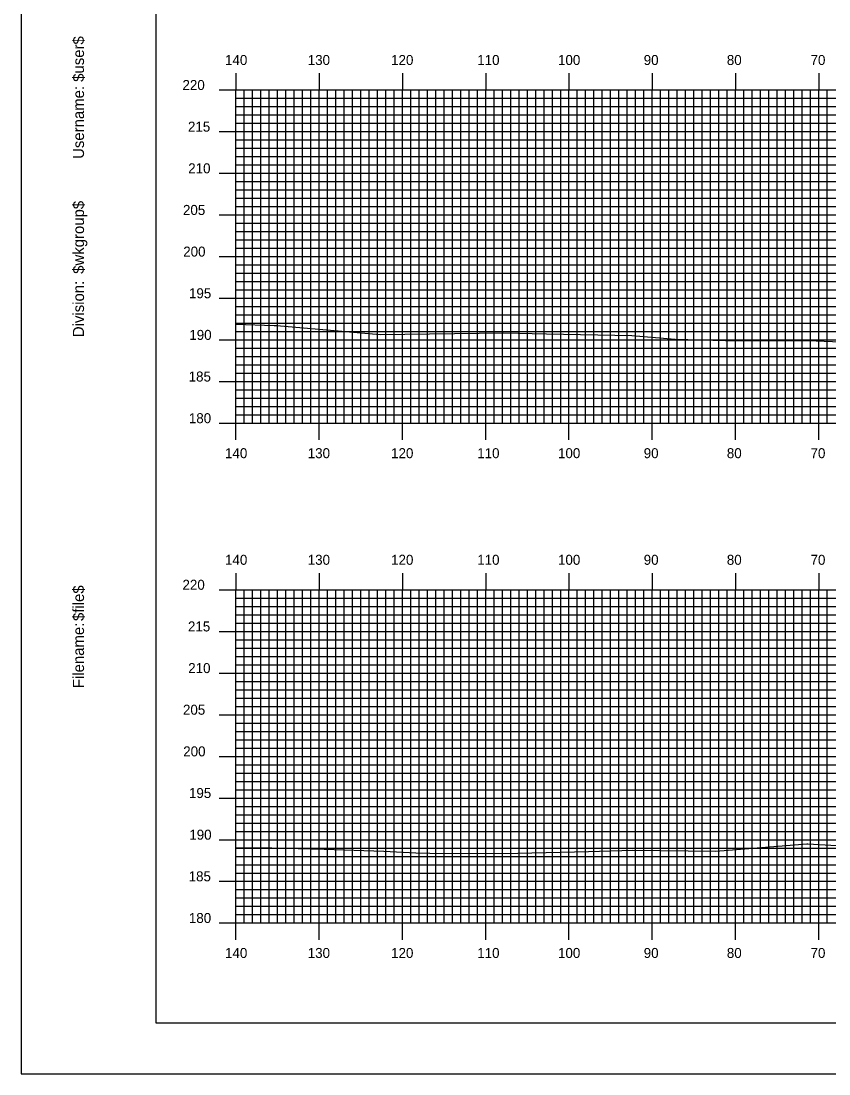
# Model space of a CAD drawing. Extents: x 1810587 to 1810930, y 442591 to 442811.
# Drawn here: x 1810586.6 to 1810683.6, y 442590.5 to 442716.9 of the extents above; entities that cross this region are included whole.
import ezdxf

# ---------------------------------------------------------------- set-up
doc = ezdxf.new("R2010")
doc.units = 0
for name, color, linetype in [('BORDER', 7, 'Continuous'), ('H_V ANNOTATION', 7, 'Continuous'), ('MAJOR', 7, 'Continuous'), ('MINOR', 7, 'Continuous'), ('PLOT BOUNDARY', 7, 'Continuous'), ('S_Roadway_Centerline', 7, 'Continuous')]:
    doc.layers.add(name, color=color, linetype=linetype)

msp = doc.modelspace()

# ---------------------------------------------------------------- linework, layer by layer
at = {"layer": 'BORDER'}
msp.add_lwpolyline([(1810602.78, 442596.67), (1810922.78, 442596.67), (1810922.78, 442806.67), (1810602.78, 442806.67)], close=True, dxfattribs=at)
at = {"layer": 'MAJOR'}
for p, q in [((1810612.38, 442710.67), (1810612.38, 442708.67)), ((1810622.38, 442710.67), (1810622.38, 442708.67)), ((1810632.38, 442710.67), (1810632.38, 442708.67)), ((1810642.38, 442710.67), (1810642.38, 442708.67)), ((1810652.38, 442710.67), (1810652.38, 442708.67)), ((1810662.38, 442710.67), (1810662.38, 442708.67)), ((1810672.38, 442710.67), (1810672.38, 442708.67)), ((1810682.38, 442710.67), (1810682.38, 442708.67)), ((1810610.37, 442708.67), (1810612.38, 442708.67)), ((1810612.38, 442708.67), (1810892.38, 442708.67)), ((1810612.38, 442668.67), (1810612.38, 442708.67)), ((1810612.38, 442668.67), (1810612.38, 442708.67)), ((1810612.38, 442708.67), (1810892.38, 442708.67)), ((1810622.38, 442668.67), (1810622.38, 442708.67)), ((1810632.38, 442668.67), (1810632.38, 442708.67)), ((1810642.38, 442668.67), (1810642.38, 442708.67)), ((1810652.38, 442668.67), (1810652.38, 442708.67)), ((1810662.38, 442668.67), (1810662.38, 442708.67)), ((1810672.38, 442668.67), (1810672.38, 442708.67)), ((1810682.38, 442668.67), (1810682.38, 442708.67)), ((1810610.37, 442703.67), (1810612.38, 442703.67)), ((1810612.38, 442703.67), (1810892.38, 442703.67)), ((1810610.37, 442698.67), (1810612.38, 442698.67)), ((1810612.38, 442698.67), (1810892.38, 442698.67)), ((1810610.37, 442693.67), (1810612.38, 442693.67)), ((1810612.38, 442693.67), (1810892.38, 442693.67)), ((1810610.37, 442688.67), (1810612.38, 442688.67)), ((1810612.38, 442688.67), (1810892.38, 442688.67)), ((1810610.37, 442683.67), (1810612.38, 442683.67)), ((1810612.38, 442683.67), (1810892.38, 442683.67)), ((1810610.37, 442678.67), (1810612.38, 442678.67)), ((1810612.38, 442678.67), (1810892.38, 442678.67)), ((1810610.37, 442673.67), (1810612.38, 442673.67)), ((1810612.38, 442673.67), (1810892.38, 442673.67)), ((1810610.37, 442668.67), (1810612.38, 442668.67)), ((1810612.38, 442668.67), (1810892.38, 442668.67)), ((1810612.38, 442668.67), (1810892.38, 442668.67)), ((1810612.38, 442666.66), (1810612.38, 442668.67)), ((1810622.38, 442666.66), (1810622.38, 442668.67)), ((1810632.38, 442666.66), (1810632.38, 442668.67)), ((1810642.38, 442666.66), (1810642.38, 442668.67)), ((1810652.38, 442666.66), (1810652.38, 442668.67)), ((1810662.38, 442666.66), (1810662.38, 442668.67)), ((1810672.38, 442666.66), (1810672.38, 442668.67)), ((1810682.38, 442666.66), (1810682.38, 442668.67)), ((1810612.38, 442650.67), (1810612.38, 442648.67)), ((1810622.38, 442650.67), (1810622.38, 442648.67)), ((1810632.38, 442650.67), (1810632.38, 442648.67)), ((1810642.38, 442650.67), (1810642.38, 442648.67)), ((1810652.38, 442650.67), (1810652.38, 442648.67)), ((1810662.38, 442650.67), (1810662.38, 442648.67)), ((1810672.38, 442650.67), (1810672.38, 442648.67)), ((1810682.38, 442650.67), (1810682.38, 442648.67)), ((1810610.37, 442648.67), (1810612.38, 442648.67)), ((1810612.38, 442648.67), (1810892.38, 442648.67)), ((1810612.38, 442608.67), (1810612.38, 442648.67)), ((1810612.38, 442608.67), (1810612.38, 442648.67)), ((1810612.38, 442648.67), (1810892.38, 442648.67)), ((1810622.38, 442608.67), (1810622.38, 442648.67)), ((1810632.38, 442608.67), (1810632.38, 442648.67)), ((1810642.38, 442608.67), (1810642.38, 442648.67)), ((1810652.38, 442608.67), (1810652.38, 442648.67)), ((1810662.38, 442608.67), (1810662.38, 442648.67)), ((1810672.38, 442608.67), (1810672.38, 442648.67)), ((1810682.38, 442608.67), (1810682.38, 442648.67)), ((1810610.37, 442643.67), (1810612.38, 442643.67)), ((1810612.38, 442643.67), (1810892.38, 442643.67)), ((1810610.37, 442638.67), (1810612.38, 442638.67)), ((1810612.38, 442638.67), (1810892.38, 442638.67)), ((1810610.37, 442633.67), (1810612.38, 442633.67)), ((1810612.38, 442633.67), (1810892.38, 442633.67)), ((1810610.37, 442628.67), (1810612.38, 442628.67)), ((1810612.38, 442628.67), (1810892.38, 442628.67)), ((1810610.37, 442623.67), (1810612.38, 442623.67)), ((1810612.38, 442623.67), (1810892.38, 442623.67)), ((1810610.37, 442618.67), (1810612.38, 442618.67)), ((1810612.38, 442618.67), (1810892.38, 442618.67)), ((1810610.37, 442613.67), (1810612.38, 442613.67)), ((1810612.38, 442613.67), (1810892.38, 442613.67)), ((1810610.37, 442608.67), (1810612.38, 442608.67)), ((1810612.38, 442608.67), (1810892.38, 442608.67)), ((1810612.38, 442608.67), (1810892.38, 442608.67)), ((1810612.38, 442606.66), (1810612.38, 442608.67)), ((1810622.38, 442606.66), (1810622.38, 442608.67)), ((1810632.38, 442606.66), (1810632.38, 442608.67)), ((1810642.38, 442606.66), (1810642.38, 442608.67)), ((1810652.38, 442606.66), (1810652.38, 442608.67)), ((1810662.38, 442606.66), (1810662.38, 442608.67)), ((1810672.38, 442606.66), (1810672.38, 442608.67)), ((1810682.38, 442606.66), (1810682.38, 442608.67))]:
    msp.add_line(p, q, dxfattribs=at)
at = {"layer": 'MINOR'}
for p, q in [((1810613.38, 442668.67), (1810613.38, 442708.67)), ((1810614.38, 442668.67), (1810614.38, 442708.67)), ((1810615.38, 442668.67), (1810615.38, 442708.67)), ((1810616.38, 442668.67), (1810616.38, 442708.67)), ((1810617.38, 442668.67), (1810617.38, 442708.67)), ((1810618.38, 442668.67), (1810618.38, 442708.67)), ((1810619.38, 442668.67), (1810619.38, 442708.67)), ((1810620.38, 442668.67), (1810620.38, 442708.67)), ((1810621.38, 442668.67), (1810621.38, 442708.67)), ((1810623.38, 442668.67), (1810623.38, 442708.67)), ((1810624.38, 442668.67), (1810624.38, 442708.67)), ((1810625.38, 442668.67), (1810625.38, 442708.67)), ((1810626.38, 442668.67), (1810626.38, 442708.67)), ((1810627.38, 442668.67), (1810627.38, 442708.67)), ((1810628.38, 442668.67), (1810628.38, 442708.67)), ((1810629.38, 442668.67), (1810629.38, 442708.67)), ((1810630.38, 442668.67), (1810630.38, 442708.67)), ((1810631.38, 442668.67), (1810631.38, 442708.67)), ((1810633.38, 442668.67), (1810633.38, 442708.67)), ((1810634.38, 442668.67), (1810634.38, 442708.67)), ((1810635.38, 442668.67), (1810635.38, 442708.67)), ((1810636.38, 442668.67), (1810636.38, 442708.67)), ((1810637.38, 442668.67), (1810637.38, 442708.67)), ((1810638.38, 442668.67), (1810638.38, 442708.67)), ((1810639.38, 442668.67), (1810639.38, 442708.67)), ((1810640.38, 442668.67), (1810640.38, 442708.67)), ((1810641.38, 442668.67), (1810641.38, 442708.67)), ((1810643.38, 442668.67), (1810643.38, 442708.67)), ((1810644.38, 442668.67), (1810644.38, 442708.67)), ((1810645.38, 442668.67), (1810645.38, 442708.67)), ((1810646.38, 442668.67), (1810646.38, 442708.67)), ((1810647.38, 442668.67), (1810647.38, 442708.67)), ((1810648.38, 442668.67), (1810648.38, 442708.67)), ((1810649.38, 442668.67), (1810649.38, 442708.67)), ((1810650.38, 442668.67), (1810650.38, 442708.67)), ((1810651.38, 442668.67), (1810651.38, 442708.67)), ((1810653.38, 442668.67), (1810653.38, 442708.67)), ((1810654.38, 442668.67), (1810654.38, 442708.67)), ((1810655.38, 442668.67), (1810655.38, 442708.67)), ((1810656.38, 442668.67), (1810656.38, 442708.67)), ((1810657.38, 442668.67), (1810657.38, 442708.67)), ((1810658.38, 442668.67), (1810658.38, 442708.67)), ((1810659.38, 442668.67), (1810659.38, 442708.67)), ((1810660.38, 442668.67), (1810660.38, 442708.67)), ((1810661.38, 442668.67), (1810661.38, 442708.67)), ((1810663.38, 442668.67), (1810663.38, 442708.67)), ((1810664.38, 442668.67), (1810664.38, 442708.67)), ((1810665.38, 442668.67), (1810665.38, 442708.67)), ((1810666.38, 442668.67), (1810666.38, 442708.67)), ((1810667.38, 442668.67), (1810667.38, 442708.67)), ((1810668.38, 442668.67), (1810668.38, 442708.67)), ((1810669.38, 442668.67), (1810669.38, 442708.67)), ((1810670.38, 442668.67), (1810670.38, 442708.67)), ((1810671.38, 442668.67), (1810671.38, 442708.67)), ((1810673.38, 442668.67), (1810673.38, 442708.67)), ((1810674.38, 442668.67), (1810674.38, 442708.67)), ((1810675.38, 442668.67), (1810675.38, 442708.67)), ((1810676.38, 442668.67), (1810676.38, 442708.67)), ((1810677.38, 442668.67), (1810677.38, 442708.67)), ((1810678.38, 442668.67), (1810678.38, 442708.67)), ((1810679.38, 442668.67), (1810679.38, 442708.67)), ((1810680.38, 442668.67), (1810680.38, 442708.67)), ((1810681.38, 442668.67), (1810681.38, 442708.67)), ((1810683.38, 442668.67), (1810683.38, 442708.67)), ((1810612.38, 442707.67), (1810892.38, 442707.67)), ((1810612.38, 442707.67), (1810614.38, 442707.67)), ((1810612.38, 442706.67), (1810892.38, 442706.67)), ((1810612.38, 442706.67), (1810614.38, 442706.67)), ((1810612.38, 442705.67), (1810892.38, 442705.67)), ((1810612.38, 442705.67), (1810614.38, 442705.67)), ((1810612.38, 442704.67), (1810892.38, 442704.67)), ((1810612.38, 442704.67), (1810614.38, 442704.67)), ((1810612.38, 442702.67), (1810892.38, 442702.67)), ((1810612.38, 442702.67), (1810614.38, 442702.67)), ((1810612.38, 442701.67), (1810892.38, 442701.67)), ((1810612.38, 442701.67), (1810614.38, 442701.67)), ((1810612.38, 442700.67), (1810892.38, 442700.67)), ((1810612.38, 442700.67), (1810614.38, 442700.67)), ((1810612.38, 442699.67), (1810892.38, 442699.67)), ((1810612.38, 442699.67), (1810614.38, 442699.67)), ((1810612.38, 442697.67), (1810892.38, 442697.67)), ((1810612.38, 442697.67), (1810614.38, 442697.67)), ((1810612.38, 442696.67), (1810892.38, 442696.67)), ((1810612.38, 442696.67), (1810614.38, 442696.67)), ((1810612.38, 442695.67), (1810892.38, 442695.67)), ((1810612.38, 442695.67), (1810614.38, 442695.67)), ((1810612.38, 442694.67), (1810892.38, 442694.67)), ((1810612.38, 442694.67), (1810614.38, 442694.67)), ((1810612.38, 442692.67), (1810892.38, 442692.67)), ((1810612.38, 442692.67), (1810614.38, 442692.67)), ((1810612.38, 442691.67), (1810892.38, 442691.67)), ((1810612.38, 442691.67), (1810614.38, 442691.67)), ((1810612.38, 442690.67), (1810892.38, 442690.67)), ((1810612.38, 442690.67), (1810614.38, 442690.67)), ((1810612.38, 442689.67), (1810892.38, 442689.67)), ((1810612.38, 442689.67), (1810614.38, 442689.67)), ((1810612.38, 442687.67), (1810892.38, 442687.67)), ((1810612.38, 442687.67), (1810614.38, 442687.67)), ((1810612.38, 442686.67), (1810892.38, 442686.67)), ((1810612.38, 442686.67), (1810614.38, 442686.67)), ((1810612.38, 442685.67), (1810892.38, 442685.67)), ((1810612.38, 442685.67), (1810614.38, 442685.67)), ((1810612.38, 442684.67), (1810892.38, 442684.67)), ((1810612.38, 442684.67), (1810614.38, 442684.67)), ((1810612.38, 442682.67), (1810892.38, 442682.67)), ((1810612.38, 442682.67), (1810614.38, 442682.67)), ((1810612.38, 442681.67), (1810892.38, 442681.67)), ((1810612.38, 442681.67), (1810614.38, 442681.67)), ((1810612.38, 442680.67), (1810892.38, 442680.67)), ((1810612.38, 442680.67), (1810614.38, 442680.67)), ((1810612.38, 442679.67), (1810892.38, 442679.67)), ((1810612.38, 442679.67), (1810614.38, 442679.67)), ((1810612.38, 442677.67), (1810892.38, 442677.67)), ((1810612.38, 442677.67), (1810614.38, 442677.67)), ((1810612.38, 442676.67), (1810892.38, 442676.67)), ((1810612.38, 442676.67), (1810614.38, 442676.67)), ((1810612.38, 442675.67), (1810892.38, 442675.67)), ((1810612.38, 442675.67), (1810614.38, 442675.67)), ((1810612.38, 442674.67), (1810892.38, 442674.67)), ((1810612.38, 442674.67), (1810614.38, 442674.67)), ((1810612.38, 442672.67), (1810892.38, 442672.67)), ((1810612.38, 442672.67), (1810614.38, 442672.67)), ((1810612.38, 442671.67), (1810892.38, 442671.67)), ((1810612.38, 442671.67), (1810614.38, 442671.67)), ((1810612.38, 442670.67), (1810892.38, 442670.67)), ((1810612.38, 442670.67), (1810614.38, 442670.67)), ((1810612.38, 442669.67), (1810892.38, 442669.67)), ((1810612.38, 442669.67), (1810614.38, 442669.67)), ((1810613.38, 442608.67), (1810613.38, 442648.67)), ((1810614.38, 442608.67), (1810614.38, 442648.67)), ((1810615.38, 442608.67), (1810615.38, 442648.67)), ((1810616.38, 442608.67), (1810616.38, 442648.67)), ((1810617.38, 442608.67), (1810617.38, 442648.67)), ((1810618.38, 442608.67), (1810618.38, 442648.67)), ((1810619.38, 442608.67), (1810619.38, 442648.67)), ((1810620.38, 442608.67), (1810620.38, 442648.67)), ((1810621.38, 442608.67), (1810621.38, 442648.67)), ((1810623.38, 442608.67), (1810623.38, 442648.67)), ((1810624.38, 442608.67), (1810624.38, 442648.67)), ((1810625.38, 442608.67), (1810625.38, 442648.67)), ((1810626.38, 442608.67), (1810626.38, 442648.67)), ((1810627.38, 442608.67), (1810627.38, 442648.67)), ((1810628.38, 442608.67), (1810628.38, 442648.67)), ((1810629.38, 442608.67), (1810629.38, 442648.67)), ((1810630.38, 442608.67), (1810630.38, 442648.67)), ((1810631.38, 442608.67), (1810631.38, 442648.67)), ((1810633.38, 442608.67), (1810633.38, 442648.67)), ((1810634.38, 442608.67), (1810634.38, 442648.67)), ((1810635.38, 442608.67), (1810635.38, 442648.67)), ((1810636.38, 442608.67), (1810636.38, 442648.67)), ((1810637.38, 442608.67), (1810637.38, 442648.67)), ((1810638.38, 442608.67), (1810638.38, 442648.67)), ((1810639.38, 442608.67), (1810639.38, 442648.67)), ((1810640.38, 442608.67), (1810640.38, 442648.67)), ((1810641.38, 442608.67), (1810641.38, 442648.67)), ((1810643.38, 442608.67), (1810643.38, 442648.67)), ((1810644.38, 442608.67), (1810644.38, 442648.67)), ((1810645.38, 442608.67), (1810645.38, 442648.67)), ((1810646.38, 442608.67), (1810646.38, 442648.67)), ((1810647.38, 442608.67), (1810647.38, 442648.67)), ((1810648.38, 442608.67), (1810648.38, 442648.67)), ((1810649.38, 442608.67), (1810649.38, 442648.67)), ((1810650.38, 442608.67), (1810650.38, 442648.67)), ((1810651.38, 442608.67), (1810651.38, 442648.67)), ((1810653.38, 442608.67), (1810653.38, 442648.67)), ((1810654.38, 442608.67), (1810654.38, 442648.67)), ((1810655.38, 442608.67), (1810655.38, 442648.67)), ((1810656.38, 442608.67), (1810656.38, 442648.67)), ((1810657.38, 442608.67), (1810657.38, 442648.67)), ((1810658.38, 442608.67), (1810658.38, 442648.67)), ((1810659.38, 442608.67), (1810659.38, 442648.67)), ((1810660.38, 442608.67), (1810660.38, 442648.67)), ((1810661.38, 442608.67), (1810661.38, 442648.67)), ((1810663.38, 442608.67), (1810663.38, 442648.67)), ((1810664.38, 442608.67), (1810664.38, 442648.67)), ((1810665.38, 442608.67), (1810665.38, 442648.67)), ((1810666.38, 442608.67), (1810666.38, 442648.67)), ((1810667.38, 442608.67), (1810667.38, 442648.67)), ((1810668.38, 442608.67), (1810668.38, 442648.67)), ((1810669.38, 442608.67), (1810669.38, 442648.67)), ((1810670.38, 442608.67), (1810670.38, 442648.67)), ((1810671.38, 442608.67), (1810671.38, 442648.67)), ((1810673.38, 442608.67), (1810673.38, 442648.67)), ((1810674.38, 442608.67), (1810674.38, 442648.67)), ((1810675.38, 442608.67), (1810675.38, 442648.67)), ((1810676.38, 442608.67), (1810676.38, 442648.67)), ((1810677.38, 442608.67), (1810677.38, 442648.67)), ((1810678.38, 442608.67), (1810678.38, 442648.67)), ((1810679.38, 442608.67), (1810679.38, 442648.67)), ((1810680.38, 442608.67), (1810680.38, 442648.67)), ((1810681.38, 442608.67), (1810681.38, 442648.67)), ((1810683.38, 442608.67), (1810683.38, 442648.67)), ((1810612.38, 442647.67), (1810892.38, 442647.67)), ((1810612.38, 442647.67), (1810614.38, 442647.67)), ((1810612.38, 442646.67), (1810892.38, 442646.67)), ((1810612.38, 442646.67), (1810614.38, 442646.67)), ((1810612.38, 442645.67), (1810892.38, 442645.67)), ((1810612.38, 442645.67), (1810614.38, 442645.67)), ((1810612.38, 442644.67), (1810892.38, 442644.67)), ((1810612.38, 442644.67), (1810614.38, 442644.67)), ((1810612.38, 442642.67), (1810892.38, 442642.67)), ((1810612.38, 442642.67), (1810614.38, 442642.67)), ((1810612.38, 442641.67), (1810892.38, 442641.67)), ((1810612.38, 442641.67), (1810614.38, 442641.67)), ((1810612.38, 442640.67), (1810892.38, 442640.67)), ((1810612.38, 442640.67), (1810614.38, 442640.67)), ((1810612.38, 442639.67), (1810892.38, 442639.67)), ((1810612.38, 442639.67), (1810614.38, 442639.67)), ((1810612.38, 442637.67), (1810892.38, 442637.67)), ((1810612.38, 442637.67), (1810614.38, 442637.67)), ((1810612.38, 442636.67), (1810892.38, 442636.67)), ((1810612.38, 442636.67), (1810614.38, 442636.67)), ((1810612.38, 442635.67), (1810892.38, 442635.67)), ((1810612.38, 442635.67), (1810614.38, 442635.67)), ((1810612.38, 442634.67), (1810892.38, 442634.67)), ((1810612.38, 442634.67), (1810614.38, 442634.67)), ((1810612.38, 442632.67), (1810892.38, 442632.67)), ((1810612.38, 442632.67), (1810614.38, 442632.67)), ((1810612.38, 442631.67), (1810892.38, 442631.67)), ((1810612.38, 442631.67), (1810614.38, 442631.67)), ((1810612.38, 442630.67), (1810892.38, 442630.67)), ((1810612.38, 442630.67), (1810614.38, 442630.67)), ((1810612.38, 442629.67), (1810892.38, 442629.67)), ((1810612.38, 442629.67), (1810614.38, 442629.67)), ((1810612.38, 442627.67), (1810892.38, 442627.67)), ((1810612.38, 442627.67), (1810614.38, 442627.67)), ((1810612.38, 442626.67), (1810892.38, 442626.67)), ((1810612.38, 442626.67), (1810614.38, 442626.67)), ((1810612.38, 442625.67), (1810892.38, 442625.67)), ((1810612.38, 442625.67), (1810614.38, 442625.67)), ((1810612.38, 442624.67), (1810892.38, 442624.67)), ((1810612.38, 442624.67), (1810614.38, 442624.67)), ((1810612.38, 442622.67), (1810892.38, 442622.67)), ((1810612.38, 442622.67), (1810614.38, 442622.67)), ((1810612.38, 442621.67), (1810892.38, 442621.67)), ((1810612.38, 442621.67), (1810614.38, 442621.67)), ((1810612.38, 442620.67), (1810892.38, 442620.67)), ((1810612.38, 442620.67), (1810614.38, 442620.67)), ((1810612.38, 442619.67), (1810892.38, 442619.67)), ((1810612.38, 442619.67), (1810614.38, 442619.67)), ((1810612.38, 442617.67), (1810892.38, 442617.67)), ((1810612.38, 442617.67), (1810614.38, 442617.67)), ((1810612.38, 442616.67), (1810892.38, 442616.67)), ((1810612.38, 442616.67), (1810614.38, 442616.67)), ((1810612.38, 442615.67), (1810892.38, 442615.67)), ((1810612.38, 442615.67), (1810614.38, 442615.67)), ((1810612.38, 442614.67), (1810892.38, 442614.67)), ((1810612.38, 442614.67), (1810614.38, 442614.67)), ((1810612.38, 442612.67), (1810892.38, 442612.67)), ((1810612.38, 442612.67), (1810614.38, 442612.67)), ((1810612.38, 442611.67), (1810892.38, 442611.67)), ((1810612.38, 442611.67), (1810614.38, 442611.67)), ((1810612.38, 442610.67), (1810892.38, 442610.67)), ((1810612.38, 442610.67), (1810614.38, 442610.67)), ((1810612.38, 442609.67), (1810892.38, 442609.67)), ((1810612.38, 442609.67), (1810614.38, 442609.67))]:
    msp.add_line(p, q, dxfattribs=at)
at = {"layer": 'PLOT BOUNDARY'}
msp.add_lwpolyline([(1810586.59, 442590.55), (1810926.59, 442590.55), (1810926.59, 442810.55), (1810586.59, 442810.55)], close=True, dxfattribs=at)
at = {"layer": 'S_Roadway_Centerline'}
for points in [[(1810612.38, 442680.56), (1810616.99, 442680.41), (1810617.32, 442680.39), (1810629.69, 442679.32), (1810644.57, 442679.5), (1810649.67, 442679.4), (1810659.94, 442679.19), (1810665.13, 442678.75), (1810671.18, 442678.59), (1810681.07, 442678.59), (1810695.92, 442678), (1810698.45, 442677.7), (1810700.45, 442677.76), (1810710.94, 442677.65), (1810723.66, 442677.96), (1810723.7, 442677.96), (1810723.74, 442677.96), (1810724.02, 442677.96), (1810743.64, 442677.87), (1810746.05, 442677.85), (1810749.12, 442677.72), (1810766.25, 442677.34), (1810773.84, 442677.41), (1810786.87, 442677.39)], [(1810612.38, 442617.7), (1810616.72, 442617.68), (1810622.99, 442617.52), (1810630.13, 442617.28), (1810634, 442617.11), (1810637.35, 442617), (1810646.22, 442617.05), (1810654.72, 442617.26), (1810660.05, 442617.42), (1810670, 442617.29), (1810680.95, 442618.18), (1810681.06, 442618.18), (1810703.1, 442616.88)]]:
    msp.add_lwpolyline(points, dxfattribs=at)

# ---------------------------------------------------------------- texts
at = {"layer": 'BORDER'}
for s, p in [('$user$', (1810594.15, 442709.65)), ('Username:', (1810594.15, 442700.4)), ('$wkgroup$', (1810594.15, 442686.6)), ('Division:', (1810594.15, 442679)), ('$file$', (1810594.15, 442644.92)), ('Filename:', (1810594.15, 442636.86))]:
    msp.add_text(s, height=1.339, rotation=90, dxfattribs=at).set_placement(p)
at = {"layer": 'H_V ANNOTATION'}
for s, p in [('140', (1810611.08, 442711.67)), ('130', (1810621.01, 442711.67)), ('120', (1810631.02, 442711.67)), ('110', (1810641.36, 442711.67)), ('100', (1810651.06, 442711.67)), ('90', (1810661.35, 442711.67)), ('80', (1810671.33, 442711.67)), ('70', (1810681.38, 442711.67)), ('220', (1810605.97, 442708.67)), ('215', (1810606.63, 442703.67)), ('210', (1810606.66, 442698.67)), ('205', (1810606.03, 442693.67)), ('200', (1810606.06, 442688.67)), ('195', (1810606.75, 442683.67)), ('190', (1810606.79, 442678.67)), ('185', (1810606.71, 442673.67)), ('180', (1810606.74, 442668.67)), ('140', (1810611.08, 442664.47)), ('130', (1810621.01, 442664.47)), ('120', (1810631.02, 442664.47)), ('110', (1810641.36, 442664.47)), ('100', (1810651.06, 442664.47)), ('90', (1810661.35, 442664.47)), ('80', (1810671.33, 442664.47)), ('70', (1810681.38, 442664.47)), ('140', (1810611.08, 442651.67)), ('130', (1810621.01, 442651.67)), ('120', (1810631.02, 442651.67)), ('110', (1810641.36, 442651.67)), ('100', (1810651.06, 442651.67)), ('90', (1810661.35, 442651.67)), ('80', (1810671.33, 442651.67)), ('70', (1810681.38, 442651.67)), ('220', (1810605.97, 442648.67)), ('215', (1810606.63, 442643.67)), ('210', (1810606.66, 442638.67)), ('205', (1810606.03, 442633.67)), ('200', (1810606.06, 442628.67)), ('195', (1810606.75, 442623.67)), ('190', (1810606.79, 442618.67)), ('185', (1810606.71, 442613.67)), ('180', (1810606.74, 442608.67)), ('140', (1810611.08, 442604.47)), ('130', (1810621.01, 442604.47)), ('120', (1810631.02, 442604.47)), ('110', (1810641.36, 442604.47)), ('100', (1810651.06, 442604.47)), ('90', (1810661.35, 442604.47)), ('80', (1810671.33, 442604.47)), ('70', (1810681.38, 442604.47))]:
    msp.add_text(s, height=1.2, dxfattribs=at).set_placement(p)
at = {"layer": 'MAJOR'}
for p in [(1810612.37, 442668.67), (1810612.37, 442608.67)]:
    msp.add_text('-', height=0.012, dxfattribs=at).set_placement(p)

doc.saveas('drawing.dxf')
